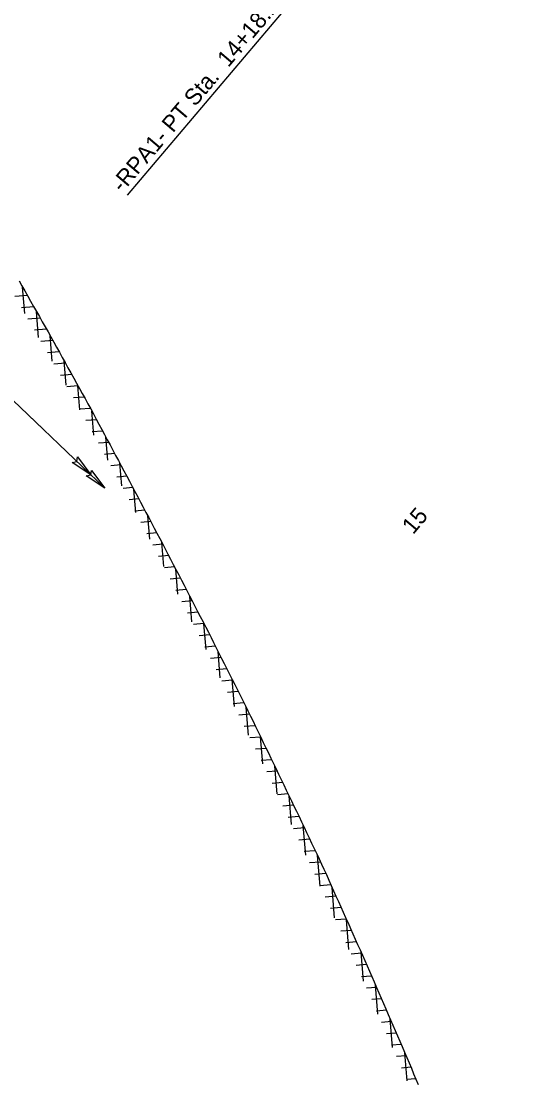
# Model space of a CAD drawing. Extents: x 1761082 to 1764358, y 421907 to 425434.
# Drawn here: x 1762735 to 1762947.2, y 422675.7 to 423126 of the extents above; entities that cross this region are included whole.
import ezdxf

# ---------------------------------------------------------------- set-up
doc = ezdxf.new("R2010")
doc.units = 0
for name, color, linetype in [('MARK HOOKS STRAIGHT RIGHT TURN ARROW CELL', 7, 'Continuous'), ('MARK UTURN ARROW CELL', 7, 'Continuous'), ('Prop Conc 4in Sidewalk', 7, 'Continuous'), ('Prop Mkg Solid White Stop Bar', 7, 'Continuous'), ('Prop Mkg Solid Yel Skip RT', 7, 'Continuous'), ('Typical Terminator CELL', 7, 'Continuous')]:
    doc.layers.add(name, color=color, linetype=linetype)

msp = doc.modelspace()

# ---------------------------------------------------------------- linework, layer by layer
at = {"layer": 'MARK UTURN ARROW CELL'}
msp.add_lwpolyline([(1762947.23, 423222.93), (1762857.28, 423143.42), (1762779.97, 423052.17)], dxfattribs=at)
at = {"layer": 'Prop Conc 4in Sidewalk'}
for p, q in [((1762736.54, 423001.8), (1762735.6, 423013.1)), ((1762737.63, 423009.53), (1762732.3, 423009.08)), ((1762740.36, 423004.73), (1762735.09, 423004.3)), ((1762743.08, 422999.94), (1762737.86, 422999.51)), ((1762742.39, 422991.68), (1762741.47, 423002.77)), ((1762745.8, 422995.15), (1762740.63, 422994.72)), ((1762748.49, 422990.36), (1762743.4, 422989.93)), ((1762748.24, 422981.56), (1762747.35, 422992.41)), ((1762751.15, 422985.56), (1762746.17, 422985.15)), ((1762754.1, 422971.43), (1762753.24, 422981.79)), ((1762753.81, 422980.76), (1762748.94, 422980.36)), ((1762756.47, 422975.96), (1762751.71, 422975.57)), ((1762759.13, 422971.17), (1762754.47, 422970.78)), ((1762759.98, 422960.96), (1762759.14, 422971.16)), ((1762761.8, 422966.37), (1762757.2, 422965.99)), ((1762764.44, 422961.57), (1762759.85, 422961.19)), ((1762765.89, 422950.26), (1762765.04, 422960.47)), ((1762767.03, 422956.77), (1762762.5, 422956.4)), ((1762769.6, 422951.97), (1762765.15, 422951.6)), ((1762772.18, 422947.16), (1762767.8, 422946.8)), ((1762771.79, 422939.55), (1762770.97, 422949.41)), ((1762774.75, 422942.36), (1762770.44, 422942)), ((1762777.32, 422937.55), (1762773.08, 422937.2)), ((1762777.71, 422928.66), (1762776.91, 422938.33)), ((1762779.9, 422932.75), (1762775.69, 422932.4)), ((1762782.46, 422927.94), (1762778.27, 422927.6)), ((1762783.66, 422917.4), (1762782.84, 422927.21)), ((1762784.99, 422923.14), (1762780.82, 422922.79)), ((1762787.53, 422918.33), (1762783.35, 422917.98)), ((1762789.61, 422906.04), (1762788.79, 422915.93)), ((1762790.06, 422913.52), (1762785.88, 422913.18)), ((1762792.6, 422908.71), (1762788.4, 422908.37)), ((1762795.59, 422894.42), (1762794.75, 422904.64)), ((1762795.13, 422903.91), (1762790.91, 422903.56)), ((1762797.67, 422899.1), (1762793.38, 422898.74)), ((1762800.18, 422894.29), (1762795.84, 422893.93)), ((1762801.58, 422882.7), (1762800.7, 422893.28)), ((1762802.67, 422889.48), (1762798.3, 422889.12)), ((1762805.15, 422884.67), (1762800.76, 422884.3)), ((1762807.64, 422879.86), (1762803.22, 422879.49)), ((1762807.56, 422870.99), (1762806.68, 422881.72)), ((1762810.13, 422875.05), (1762805.68, 422874.68)), ((1762812.62, 422870.23), (1762808.14, 422869.86)), ((1762813.55, 422859.26), (1762812.65, 422870.17)), ((1762815.1, 422865.42), (1762810.6, 422865.05)), ((1762817.54, 422860.61), (1762813.06, 422860.24)), ((1762819.96, 422855.79), (1762815.49, 422855.42)), ((1762819.57, 422847.19), (1762818.64, 422858.42)), ((1762822.39, 422850.97), (1762817.88, 422850.6)), ((1762824.81, 422846.16), (1762820.27, 422845.78)), ((1762825.59, 422835.01), (1762824.64, 422846.49)), ((1762827.23, 422841.34), (1762822.65, 422840.96)), ((1762829.65, 422836.52), (1762825.03, 422836.14)), ((1762831.62, 422822.82), (1762830.65, 422834.55)), ((1762832.07, 422831.71), (1762827.41, 422831.32)), ((1762834.42, 422826.88), (1762829.8, 422826.5)), ((1762836.75, 422822.06), (1762832.18, 422821.68)), ((1762837.65, 422810.61), (1762836.69, 422822.19)), ((1762839.08, 422817.24), (1762834.56, 422816.86)), ((1762841.4, 422812.41), (1762836.94, 422812.04)), ((1762843.73, 422807.59), (1762839.3, 422807.22)), ((1762843.72, 422797.88), (1762842.74, 422809.63)), ((1762846.05, 422802.76), (1762841.59, 422802.39)), ((1762848.38, 422797.94), (1762843.86, 422797.56)), ((1762849.81, 422784.93), (1762848.8, 422797.06)), ((1762850.71, 422793.11), (1762846.13, 422792.73)), ((1762853.02, 422788.29), (1762848.4, 422787.9)), ((1762855.33, 422783.46), (1762850.67, 422783.08)), ((1762855.89, 422771.97), (1762854.86, 422784.44)), ((1762857.63, 422778.63), (1762852.94, 422778.25)), ((1762859.93, 422773.81), (1762855.21, 422773.42)), ((1762862.01, 422758.75), (1762860.93, 422771.71)), ((1762862.22, 422768.98), (1762857.48, 422768.59)), ((1762864.41, 422764.14), (1762859.72, 422763.76)), ((1762866.58, 422759.31), (1762861.93, 422758.92)), ((1762868.13, 422745.32), (1762867.07, 422758.22)), ((1762868.75, 422754.47), (1762864.13, 422754.09)), ((1762870.91, 422749.63), (1762866.34, 422749.25)), ((1762873.08, 422744.79), (1762868.54, 422744.42)), ((1762874.26, 422731.88), (1762873.22, 422744.49)), ((1762875.25, 422739.96), (1762870.75, 422739.58)), ((1762877.42, 422735.12), (1762872.95, 422734.75)), ((1762879.58, 422730.28), (1762875.16, 422729.91)), ((1762880.39, 422718.42), (1762879.37, 422730.75)), ((1762881.74, 422725.44), (1762877.36, 422725.08)), ((1762883.85, 422720.6), (1762879.57, 422720.24)), ((1762885.96, 422715.76), (1762881.75, 422715.41)), ((1762886.57, 422704.45), (1762885.55, 422716.68)), ((1762888.06, 422710.91), (1762883.9, 422710.57)), ((1762890.16, 422706.07), (1762886.01, 422705.73)), ((1762892.76, 422690.24), (1762891.75, 422702.41)), ((1762892.26, 422701.23), (1762888.12, 422700.88)), ((1762894.36, 422696.38), (1762890.23, 422696.04)), ((1762896.45, 422691.54), (1762892.34, 422691.2)), ((1762898.5, 422686.69), (1762894.45, 422686.36)), ((1762898.95, 422676.03), (1762897.97, 422687.96)), ((1762900.56, 422681.84), (1762896.56, 422681.51)), ((1762902.62, 422677), (1762898.67, 422676.67))]:
    msp.add_line(p, q, dxfattribs=at)
at = {"layer": 'Prop Mkg Solid White Stop Bar'}
msp.add_lwpolyline([(1762734.09, 423015.77), (1762735.32, 423013.59), (1762736.56, 423011.42), (1762737.79, 423009.25), (1762739.03, 423007.07), (1762740.26, 423004.9), (1762741.5, 423002.73), (1762742.73, 423000.55), (1762743.97, 422998.38), (1762745.2, 422996.21), (1762746.42, 422994.06), (1762747.63, 422991.91), (1762748.83, 422989.75), (1762750.04, 422987.57), (1762751.25, 422985.39), (1762752.46, 422983.2), (1762753.67, 422981.02), (1762754.89, 422978.83), (1762756.1, 422976.64), (1762757.31, 422974.46), (1762758.52, 422972.27), (1762759.74, 422970.08), (1762760.95, 422967.9), (1762762.16, 422965.72), (1762763.36, 422963.55), (1762764.54, 422961.4), (1762765.7, 422959.25), (1762766.88, 422957.06), (1762768.05, 422954.86), (1762769.23, 422952.65), (1762770.42, 422950.45), (1762771.6, 422948.25), (1762772.78, 422946.04), (1762773.96, 422943.84), (1762775.14, 422941.64), (1762776.32, 422939.43), (1762777.5, 422937.23), (1762778.68, 422935.02), (1762779.86, 422932.82), (1762781.03, 422930.63), (1762782.19, 422928.45), (1762783.35, 422926.25), (1762784.51, 422924.05), (1762785.68, 422921.83), (1762786.85, 422919.62), (1762788.01, 422917.41), (1762789.18, 422915.2), (1762790.34, 422912.99), (1762791.51, 422910.78), (1762792.68, 422908.57), (1762793.84, 422906.36), (1762795.01, 422904.15), (1762796.17, 422901.94), (1762797.34, 422899.73), (1762798.49, 422897.54), (1762799.63, 422895.35), (1762800.77, 422893.14), (1762801.92, 422890.93), (1762803.07, 422888.71), (1762804.21, 422886.49), (1762805.36, 422884.27), (1762806.51, 422882.05), (1762807.66, 422879.83), (1762808.81, 422877.6), (1762809.95, 422875.38), (1762811.1, 422873.16), (1762812.25, 422870.94), (1762813.4, 422868.73), (1762814.54, 422866.52), (1762815.66, 422864.33), (1762816.77, 422862.13), (1762817.89, 422859.91), (1762819.01, 422857.68), (1762820.13, 422855.45), (1762821.26, 422853.22), (1762822.38, 422850.98), (1762823.5, 422848.75), (1762824.63, 422846.52), (1762825.75, 422844.29), (1762826.87, 422842.05), (1762828, 422839.82), (1762829.12, 422837.59), (1762830.24, 422835.36), (1762831.35, 422833.14), (1762832.44, 422830.95), (1762833.52, 422828.76), (1762834.59, 422826.53), (1762835.68, 422824.28), (1762836.76, 422822.03), (1762837.85, 422819.78), (1762838.93, 422817.53), (1762840.02, 422815.28), (1762841.1, 422813.03), (1762842.19, 422810.78), (1762843.28, 422808.52), (1762844.36, 422806.27), (1762845.45, 422804.02), (1762846.53, 422801.77), (1762847.62, 422799.52), (1762848.7, 422797.27), (1762849.79, 422795.01), (1762850.87, 422792.77), (1762851.95, 422790.52), (1762853.03, 422788.28), (1762854.1, 422786.04), (1762855.17, 422783.78), (1762856.25, 422781.53), (1762857.33, 422779.27), (1762858.4, 422777.01), (1762859.48, 422774.76), (1762860.56, 422772.5), (1762861.61, 422770.29), (1762862.62, 422768.12), (1762863.62, 422765.91), (1762864.64, 422763.64), (1762865.66, 422761.36), (1762866.68, 422759.08), (1762867.7, 422756.8), (1762868.73, 422754.51), (1762869.75, 422752.23), (1762870.77, 422749.95), (1762871.79, 422747.67), (1762872.81, 422745.39), (1762873.84, 422743.11), (1762874.86, 422740.83), (1762875.88, 422738.55), (1762876.9, 422736.27), (1762877.92, 422733.99), (1762878.95, 422731.7), (1762879.97, 422729.42), (1762880.98, 422727.16), (1762881.97, 422724.92), (1762882.96, 422722.66), (1762883.95, 422720.38), (1762884.95, 422718.08), (1762885.94, 422715.79), (1762886.94, 422713.5), (1762887.93, 422711.21), (1762888.93, 422708.91), (1762889.92, 422706.62), (1762890.92, 422704.33), (1762891.91, 422702.04), (1762892.91, 422699.74), (1762893.9, 422697.45), (1762894.89, 422695.17), (1762895.86, 422692.9), (1762896.83, 422690.63), (1762897.81, 422688.33), (1762898.78, 422686.03), (1762899.76, 422683.73), (1762900.74, 422681.43), (1762901.72, 422679.13), (1762902.69, 422676.83), (1762903.67, 422674.52)], dxfattribs=at)
at = {"layer": 'Prop Mkg Solid Yel Skip RT'}
msp.add_line((1762688.61, 423005.9), (1762770.55, 422927.64), dxfattribs=at)
at = {"layer": 'Typical Terminator CELL'}
for points in [[(1762758.94, 422940.97), (1762764.6, 422933.33), (1762756.63, 422938.63), (1762758.65, 422939.01)], [(1762764.89, 422935.28), (1762770.55, 422927.64), (1762762.58, 422932.95), (1762764.6, 422933.33)]]:
    msp.add_lwpolyline(points, close=True, dxfattribs=at)

# ---------------------------------------------------------------- texts
at = {"layer": 'MARK HOOKS STRAIGHT RIGHT TURN ARROW CELL'}
msp.add_text('15', height=7, rotation=50.0525, dxfattribs=at).set_placement((1762901.52, 422907.75))
at = {"layer": 'MARK UTURN ARROW CELL'}
msp.add_text('-RPA1- PT Sta.  14+18.27', height=7, rotation=49.7301, dxfattribs=at).set_placement((1762777.95, 423052.88))

doc.saveas('drawing.dxf')
